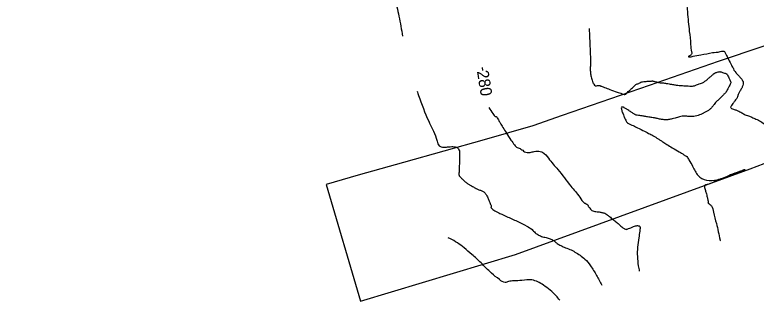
# Model space of a CAD drawing. Extents: x -478464 to -472469, y -1118040 to -1113785.
# Drawn here: x -476356.8 to -476101.8, y -1115350.3 to -1115251.7 of the extents above; entities that cross this region are included whole.
import ezdxf

# ---------------------------------------------------------------- set-up
doc = ezdxf.new("R2010")
doc.units = 0
for name, color, linetype in [('ObPÚ', 7, 'Continuous'), ('Vrstevnice_hlavni', 7, 'Continuous'), ('Vrstevnice_popis', 7, 'Continuous'), ('Vrstevnice_vedlejsi', 7, 'Continuous')]:
    doc.layers.add(name, color=color, linetype=linetype)

msp = doc.modelspace()

# ---------------------------------------------------------------- linework, layer by layer
at = {"layer": 'ObPÚ'}
msp.add_lwpolyline([(-476068.7, -1115252.31), (-476114.88, -1115267.73), (-476138.618, -1115276.003), (-476141.91, -1115277.15), (-476168.45, -1115286.39), (-476178.6, -1115289.93), (-476195.38, -1115294.7), (-476223.04, -1115302.55), (-476238.65, -1115306.98), (-476249.64, -1115310.1), (-476237.84, -1115350.34), (-476184.5, -1115334.29), (-476103.79, -1115304.74), (-476065.34, -1115290.09)], dxfattribs=at)
at = {"layer": 'Vrstevnice_hlavni'}
msp.add_line((-476196.015, -1115269.846), (-476195.861, -1115270.85), dxfattribs=at)
msp.add_spline([(-476193.757, -1115283.639), (-476192.399, -1115285.697), (-476191.876, -1115286.389), (-476191.509, -1115286.744), (-476191.298, -1115286.761), (-476191.153, -1115286.774), (-476191.075, -1115286.783), (-476191.063, -1115286.789), (-476190.853, -1115287.151), (-476190.446, -1115287.871), (-476189.842, -1115288.948), (-476188.923, -1115290.467), (-476187.688, -1115292.429), (-476186.137, -1115294.833), (-476184.891, -1115296.504), (-476183.948, -1115297.443), (-476183.309, -1115297.648), (-476182.68, -1115297.954), (-476182.06, -1115298.362), (-476181.45, -1115298.872), (-476180.595, -1115299.114), (-476179.497, -1115299.088), (-476178.155, -1115298.795), (-476176.997, -1115298.69), (-476176.025, -1115298.773), (-476175.238, -1115299.045), (-476173.224, -1115301.122), (-476169.984, -1115305.003), (-476165.518, -1115310.689), (-476162.449, -1115314.535), (-476160.779, -1115316.54), (-476160.507, -1115316.704), (-476160.264, -1115316.845), (-476160.048, -1115316.962), (-476159.86, -1115317.056), (-476159.707, -1115317.19), (-476159.59, -1115317.365), (-476159.508, -1115317.58), (-476159.311, -1115317.896), (-476158.998, -1115318.315), (-476158.57, -1115318.834), (-476158.007, -1115319.207), (-476157.308, -1115319.433), (-476156.473, -1115319.513), (-476155.76, -1115319.601), (-476155.169, -1115319.698), (-476154.699, -1115319.804), (-476154.303, -1115319.906), (-476153.978, -1115320.004), (-476153.727, -1115320.098), (-476153.145, -1115320.495), (-476152.232, -1115321.193), (-476150.988, -1115322.193), (-476149.831, -1115323.145), (-476148.761, -1115324.046), (-476147.778, -1115324.899), (-476147.017, -1115325.426), (-476146.478, -1115325.629), (-476146.16, -1115325.507), (-476145.635, -1115325.303), (-476144.904, -1115325.017), (-476143.967, -1115324.649), (-476143.233, -1115324.414), (-476142.702, -1115324.312), (-476142.375, -1115324.342), (-476142.123, -1115324.398), (-476141.945, -1115324.481), (-476141.842, -1115324.59), (-476141.767, -1115324.715), (-476141.722, -1115324.858), (-476141.705, -1115325.018), (-476141.842, -1115326.221), (-476142.131, -1115328.466), (-476142.574, -1115331.753), (-476142.636, -1115334.999), (-476142.32, -1115338.203), (-476141.962, -1115339.984)], degree=3, dxfattribs=at)
at = {"layer": 'Vrstevnice_vedlejsi'}
for points in [[(-476075.436, -1115157.873), (-476077.562, -1115158.907), (-476079.639, -1115159.964), (-476081.666, -1115161.045), (-476083.644, -1115162.149), (-476085.921, -1115163.289), (-476088.498, -1115164.465), (-476091.373, -1115165.676), (-476093.656, -1115166.843), (-476095.346, -1115167.967), (-476096.444, -1115169.047), (-476097.921, -1115170.165), (-476099.777, -1115171.319), (-476102.012, -1115172.511), (-476105.743, -1115173.677), (-476110.97, -1115174.816), (-476117.692, -1115175.928), (-476122.561, -1115177.005), (-476125.576, -1115178.045), (-476126.738, -1115179.05), (-476129.738, -1115180.989), (-476134.578, -1115183.864), (-476141.257, -1115187.673), (-476147.035, -1115190.356), (-476151.912, -1115191.911), (-476155.888, -1115192.338), (-476158.789, -1115192.754), (-476160.614, -1115193.159), (-476161.364, -1115193.552), (-476162.517, -1115193.939), (-476164.073, -1115194.319), (-476166.032, -1115194.693), (-476167.609, -1115195.158), (-476168.804, -1115195.715), (-476169.616, -1115196.364), (-476170.816, -1115197.116), (-476172.405, -1115197.973), (-476174.383, -1115198.934), (-476179.537, -1115202.555), (-476187.868, -1115208.836), (-476199.377, -1115217.776), (-476207.75, -1115223.932), (-476212.989, -1115227.302), (-476215.093, -1115227.888), (-476217.31, -1115229.046), (-476219.639, -1115230.776), (-476222.081, -1115233.079), (-476224.102, -1115235.091), (-476225.704, -1115236.812), (-476226.884, -1115238.243), (-476227.475, -1115239.561), (-476227.475, -1115240.767), (-476226.885, -1115241.861), (-476225.939, -1115245.662), (-476224.639, -1115252.17), (-476223.41, -1115259.087)], [(-476327.473, -1115168.696), (-476329.504, -1115168.15), (-476331.355, -1115167.757), (-476333.026, -1115167.517), (-476334.516, -1115167.429), (-476335.694, -1115167.418), (-476336.557, -1115167.482), (-476337.107, -1115167.623), (-476338.859, -1115167.867), (-476341.812, -1115168.215), (-476345.968, -1115168.668), (-476348.868, -1115168.973), (-476350.514, -1115169.133), (-476350.905, -1115169.146), (-476351.565, -1115169.254), (-476352.495, -1115169.457), (-476353.694, -1115169.755), (-476355.366, -1115170.663), (-476357.511, -1115172.179), (-476360.129, -1115174.306), (-476363.1, -1115176.798), (-476366.424, -1115179.657), (-476370.101, -1115182.883), (-476375.4, -1115186.443), (-476382.321, -1115190.337), (-476390.863, -1115194.566), (-476396.652, -1115197.445), (-476399.688, -1115198.974), (-476399.971, -1115199.154), (-476400.201, -1115199.316), (-476400.377, -1115199.461), (-476400.5, -1115199.588), (-476400.639, -1115199.703), (-476400.797, -1115199.808), (-476400.971, -1115199.902), (-476403.048, -1115202.383), (-476407.029, -1115207.252), (-476412.913, -1115214.508), (-476418.066, -1115221.099), (-476422.487, -1115227.024), (-476426.176, -1115232.285), (-476429.359, -1115236.354), (-476432.037, -1115239.231), (-476434.209, -1115240.916), (-476436.447, -1115242.554), (-476438.753, -1115244.145), (-476441.124, -1115245.69), (-476442.942, -1115247.528), (-476444.207, -1115249.66), (-476444.917, -1115252.086), (-476445.62, -1115255.263), (-476446.315, -1115259.192), (-476447.003, -1115263.872), (-476447.667, -1115266.918), (-476448.308, -1115268.33), (-476448.925, -1115268.107), (-476449.337, -1115267.958), (-476449.542, -1115267.883), (-476449.542, -1115267.884), (-476449.447, -1115268.421), (-476449.255, -1115269.495), (-476448.968, -1115271.106), (-476448.944, -1115271.994)], [(-476290.943, -1115168.232), (-476292.036, -1115168.129), (-476293.289, -1115168.17), (-476294.704, -1115168.355), (-476296.28, -1115168.684), (-476298.044, -1115169.506), (-476299.998, -1115170.82), (-476302.142, -1115172.626), (-476303.749, -1115173.838), (-476304.822, -1115174.454), (-476305.36, -1115174.476), (-476306.141, -1115174.653), (-476307.165, -1115174.987), (-476308.432, -1115175.476), (-476310.431, -1115176.469), (-476313.163, -1115177.965), (-476316.627, -1115179.965), (-476319.342, -1115180.948), (-476321.309, -1115180.916), (-476322.528, -1115179.868), (-476324.355, -1115178.896), (-476326.789, -1115178.002), (-476329.831, -1115177.184), (-476332.146, -1115176.734), (-476333.735, -1115176.651), (-476334.597, -1115176.934), (-476335.575, -1115177.335), (-476336.67, -1115177.853), (-476337.881, -1115178.489), (-476340.138, -1115179.828), (-476343.441, -1115181.87), (-476347.791, -1115184.616), (-476351.193, -1115186.546), (-476353.648, -1115187.661), (-476355.156, -1115187.959), (-476356.569, -1115188.49), (-476357.888, -1115189.253), (-476359.112, -1115190.247), (-476360.257, -1115191.198), (-476361.323, -1115192.106), (-476362.309, -1115192.972), (-476363.814, -1115193.968), (-476365.837, -1115195.095), (-476368.378, -1115196.353), (-476371.783, -1115197.918), (-476376.05, -1115199.79), (-476381.181, -1115201.968), (-476385.269, -1115204.296), (-476388.314, -1115206.773), (-476390.316, -1115209.399), (-476391.767, -1115211.232), (-476392.667, -1115212.272), (-476393.014, -1115212.519), (-476394.789, -1115214.333), (-476397.991, -1115217.713), (-476402.619, -1115222.659), (-476406.002, -1115226.323), (-476408.139, -1115228.705), (-476409.031, -1115229.805), (-476409.796, -1115230.781), (-476410.434, -1115231.632), (-476410.944, -1115232.36), (-476411.453, -1115232.976), (-476411.961, -1115233.481), (-476412.467, -1115233.874), (-476413.193, -1115235.547), (-476414.139, -1115238.502), (-476415.303, -1115242.737), (-476416.343, -1115247.381), (-476417.259, -1115252.434), (-476418.049, -1115257.897), (-476418.052, -1115258.256)], [(-476125.929, -1115243.884), (-476125.807, -1115246.158), (-476125.427, -1115250.782), (-476124.774, -1115257.383), (-476124.301, -1115261.931), (-476124.008, -1115264.426), (-476123.894, -1115264.868), (-476123.981, -1115265.246), (-476124.269, -1115265.56), (-476124.757, -1115265.811), (-476125.029, -1115265.996), (-476125.083, -1115266.115), (-476124.92, -1115266.169), (-476123.491, -1115265.956), (-476120.797, -1115265.476), (-476116.836, -1115264.728), (-476114.123, -1115264.363), (-476112.657, -1115264.382), (-476112.438, -1115264.783), (-476111.966, -1115265.692), (-476111.241, -1115267.111), (-476110.263, -1115269.038), (-476109.58, -1115270.343), (-476109.193, -1115271.027), (-476109.102, -1115271.089), (-476109.038, -1115271.136), (-476109.003, -1115271.169), (-476108.995, -1115271.186), (-476108.962, -1115271.248), (-476108.904, -1115271.357), (-476108.821, -1115271.512), (-476108.502, -1115271.894), (-476107.946, -1115272.505), (-476107.155, -1115273.343), (-476106.601, -1115274.081), (-476106.285, -1115274.719), (-476106.206, -1115275.258), (-476106.359, -1115275.986), (-476106.744, -1115276.905)], [(-476159.242, -1115256.374), (-476159.054, -1115259.908), (-476158.82, -1115265.295), (-476158.75, -1115268.706), (-476158.845, -1115270.139), (-476158.769, -1115271.604), (-476158.523, -1115273.101), (-476158.106, -1115274.629), (-476157.613, -1115275.635), (-476157.044, -1115276.119), (-476156.398, -1115276.081), (-476155.961, -1115276.055), (-476155.733, -1115276.04), (-476155.713, -1115276.036), (-476155.581, -1115276.081), (-476155.338, -1115276.173), (-476154.983, -1115276.314), (-476153.911, -1115276.714), (-476152.122, -1115277.373), (-476149.617, -1115278.29), (-476147.877, -1115278.87), (-476146.903, -1115279.111), (-476146.694, -1115279.015), (-476146.533, -1115278.92), (-476146.42, -1115278.827), (-476146.354, -1115278.736), (-476146.034, -1115278.42), (-476145.458, -1115277.878), (-476144.627, -1115277.111), (-476144.009, -1115276.53), (-476143.606, -1115276.135), (-476143.416, -1115275.928), (-476143.115, -1115275.721), (-476142.7, -1115275.515), (-476142.174, -1115275.31), (-476141.777, -1115275.132), (-476141.512, -1115274.98), (-476141.376, -1115274.855), (-476140.853, -1115274.744), (-476139.943, -1115274.647), (-476138.645, -1115274.565), (-476137.773, -1115274.512), (-476137.326, -1115274.488), (-476137.304, -1115274.493), (-476137.022, -1115274.564), (-476136.479, -1115274.699), (-476135.676, -1115274.9), (-476135.01, -1115275.037), (-476134.48, -1115275.109), (-476134.087, -1115275.117), (-476133.301, -1115275.213), (-476132.123, -1115275.399), (-476130.553, -1115275.673), (-476129.267, -1115275.873), (-476128.264, -1115275.998), (-476127.545, -1115276.049), (-476126.691, -1115276.105), (-476125.702, -1115276.169), (-476124.578, -1115276.238), (-476123.673, -1115276.222), (-476122.988, -1115276.122), (-476122.522, -1115275.938), (-476121.968, -1115275.735), (-476121.325, -1115275.516), (-476120.594, -1115275.279), (-476119.818, -1115274.872), (-476118.996, -1115274.295), (-476118.13, -1115273.548), (-476117.407, -1115272.922), (-476116.827, -1115272.417), (-476116.391, -1115272.033), (-476115.924, -1115271.733), (-476115.425, -1115271.516), (-476114.896, -1115271.383), (-476114.504, -1115271.301), (-476114.247, -1115271.269), (-476114.127, -1115271.287), (-476113.822, -1115271.374), (-476113.331, -1115271.529), (-476112.656, -1115271.752), (-476112.177, -1115271.921), (-476111.894, -1115272.035), (-476111.807, -1115272.094), (-476111.623, -1115272.416), (-476111.341, -1115273)], [(-476111.341, -1115273), (-476110.962, -1115273.848), (-476110.694, -1115274.441), (-476110.537, -1115274.78), (-476110.491, -1115274.865), (-476110.47, -1115274.959), (-476110.475, -1115275.062), (-476110.506, -1115275.174), (-476110.69, -1115275.573), (-476111.03, -1115276.26), (-476111.524, -1115277.233), (-476111.877, -1115277.912), (-476112.088, -1115278.296), (-476112.158, -1115278.386), (-476112.514, -1115278.752), (-476113.156, -1115279.397), (-476114.085, -1115280.319), (-476114.761, -1115280.979), (-476115.186, -1115281.379), (-476115.36, -1115281.517), (-476115.713, -1115281.919), (-476116.247, -1115282.585), (-476116.962, -1115283.514), (-476117.741, -1115284.291), (-476118.584, -1115284.915), (-476119.493, -1115285.387), (-476120.392, -1115285.812), (-476121.284, -1115286.191), (-476122.167, -1115286.523), (-476123.251, -1115286.707), (-476124.536, -1115286.741), (-476126.022, -1115286.628), (-476127.231, -1115286.643), (-476128.162, -1115286.786), (-476128.816, -1115287.059), (-476129.654, -1115287.316), (-476130.678, -1115287.555), (-476131.887, -1115287.779), (-476133.124, -1115287.833), (-476134.388, -1115287.719), (-476135.68, -1115287.435), (-476136.751, -1115287.215), (-476137.602, -1115287.058), (-476138.232, -1115286.963), (-476139.134, -1115286.827), (-476140.308, -1115286.649), (-476141.754, -1115286.429), (-476142.752, -1115286.26), (-476143.303, -1115286.142), (-476143.406, -1115286.075), (-476143.876, -1115285.775), (-476144.711, -1115285.24), (-476145.912, -1115284.47), (-476146.719, -1115283.95), (-476147.131, -1115283.678), (-476147.149, -1115283.654), (-476147.194, -1115283.626), (-476147.267, -1115283.594), (-476147.366, -1115283.557), (-476147.542, -1115283.533), (-476147.795, -1115283.522), (-476148.124, -1115283.524), (-476148.141, -1115284.035), (-476147.848, -1115285.056), (-476147.243, -1115286.586), (-476146.785, -1115287.691), (-476146.474, -1115288.372), (-476146.31, -1115288.628), (-476146.156, -1115288.817), (-476146.012, -1115288.938), (-476145.878, -1115288.992), (-476144.948, -1115289.442), (-476143.224, -1115290.289), (-476140.705, -1115291.532), (-476138.75, -1115292.524), (-476137.361, -1115293.265), (-476136.537, -1115293.756), (-476135.685, -1115294.285), (-476134.806, -1115294.853), (-476133.899, -1115295.46), (-476132.503, -1115296.342), (-476130.618, -1115297.498), (-476128.243, -1115298.929), (-476126.641, -1115299.885), (-476125.811, -1115300.366), (-476125.755, -1115300.372), (-476125.7, -1115300.405), (-476125.646, -1115300.464), (-476125.594, -1115300.551), (-476124.922, -1115301.679), (-476123.631, -1115303.848), (-476121.721, -1115307.059), (-476118.902, -1115308.612), (-476115.176, -1115308.508), (-476110.541, -1115306.747), (-476107.432, -1115305.567), (-476105.848, -1115304.97)], [(-476106.744, -1115276.905), (-476107.361, -1115278.014), (-476107.805, -1115278.877), (-476108.078, -1115279.493), (-476108.177, -1115279.862), (-476108.25, -1115280.122), (-476108.297, -1115280.271), (-476108.317, -1115280.311), (-476108.573, -1115280.647), (-476109.065, -1115281.28), (-476109.793, -1115282.209), (-476110.279, -1115282.913), (-476110.525, -1115283.392), (-476110.528, -1115283.645), (-476110.197, -1115283.923), (-476109.532, -1115284.226), (-476108.532, -1115284.553), (-476107.69, -1115284.894), (-476107.005, -1115285.251), (-476106.478, -1115285.622), (-476105.861, -1115285.956), (-476105.153, -1115286.251), (-476104.354, -1115286.507), (-476103.257, -1115286.96), (-476101.863, -1115287.61), (-476100.172, -1115288.455), (-476098.717, -1115289.598), (-476097.498, -1115291.039), (-476096.516, -1115292.777), (-476095.725, -1115294.323), (-476095.126, -1115295.678), (-476094.718, -1115296.841), (-476094.281, -1115297.767), (-476093.815, -1115298.456), (-476093.319, -1115298.907), (-476093.04, -1115299.473), (-476092.976, -1115300.153), (-476093.128, -1115300.947), (-476092.975, -1115301.971), (-476092.517, -1115303.223), (-476091.755, -1115304.704), (-476090.913, -1115306.661), (-476089.99, -1115309.094), (-476088.988, -1115312.004), (-476088.293, -1115314.278), (-476087.906, -1115315.919), (-476087.826, -1115316.925), (-476087.506, -1115318.414), (-476087.193, -1115319.54)], [(-476218.376, -1115278.038), (-476217.875, -1115279.456), (-476214.425, -1115288.313), (-476211.835, -1115294.229), (-476210.106, -1115297.205), (-476209.237, -1115297.241), (-476208.349, -1115297.236), (-476207.441, -1115297.189), (-476206.512, -1115297.099), (-476205.696, -1115297.136), (-476204.991, -1115297.297), (-476204.399, -1115297.584), (-476203.999, -1115298.149), (-476203.792, -1115298.991), (-476203.779, -1115300.111), (-476203.805, -1115301.478), (-476203.871, -1115303.093), (-476203.978, -1115304.956), (-476204.004, -1115306.275), (-476203.949, -1115307.051), (-476203.815, -1115307.284), (-476203.415, -1115307.714), (-476202.75, -1115308.342), (-476201.819, -1115309.168), (-476200.943, -1115309.859), (-476200.122, -1115310.415), (-476199.355, -1115310.837), (-476198.758, -1115311.169), (-476198.331, -1115311.411), (-476198.073, -1115311.564), (-476197.577, -1115311.782), (-476196.841, -1115312.065), (-476195.867, -1115312.414), (-476195.041, -1115313.077), (-476194.362, -1115314.054), (-476193.831, -1115315.346), (-476193.423, -1115316.323), (-476193.136, -1115316.986), (-476192.972, -1115317.333), (-476192.894, -1115317.625), (-476192.903, -1115317.861)], [(-476105.848, -1115304.97), (-476105.79, -1115304.953), (-476105.742, -1115304.95), (-476105.706, -1115304.96), (-476105.681, -1115304.983), (-476105.665, -1115305.007), (-476105.66, -1115305.032), (-476105.665, -1115305.057), (-476105.684, -1115305.087), (-476105.717, -1115305.122), (-476105.765, -1115305.16), (-476107.334, -1115305.771), (-476110.427, -1115306.953), (-476115.042, -1115308.707), (-476118.091, -1115309.993), (-476119.575, -1115310.812), (-476119.492, -1115311.162), (-476119.302, -1115311.898), (-476119.003, -1115313.019), (-476118.597, -1115314.525), (-476118.349, -1115315.58), (-476118.261, -1115316.183), (-476118.333, -1115316.335), (-476118.325, -1115316.469), (-476118.238, -1115316.585), (-476118.073, -1115316.683), (-476117.836, -1115316.872), (-476117.529, -1115317.152), (-476117.151, -1115317.523), (-476116.463, -1115319.666), (-476115.466, -1115323.582), (-476114.16, -1115329.271), (-476114.085, -1115329.578)], [(-476192.903, -1115317.861), (-476192.999, -1115318.042), (-476192.816, -1115318.327), (-476192.354, -1115318.716), (-476191.613, -1115319.21), (-476189.891, -1115320.089), (-476187.188, -1115321.354), (-476183.505, -1115323.005), (-476180.713, -1115324.453), (-476178.814, -1115325.697), (-476177.806, -1115326.737), (-476176.612, -1115327.549), (-476175.23, -1115328.132), (-476173.662, -1115328.486), (-476172.346, -1115328.961), (-476171.282, -1115329.555), (-476170.47, -1115330.27), (-476169.305, -1115330.996), (-476167.786, -1115331.732), (-476165.913, -1115332.48), (-476164.102, -1115333.412), (-476162.353, -1115334.527), (-476160.666, -1115335.826), (-476158.775, -1115338.132), (-476156.681, -1115341.444), (-476154.893, -1115344.811)], [(-476169.317, -1115349.984), (-476170.582, -1115348.511), (-476174.959, -1115344.81), (-476178.893, -1115343.028), (-476182.384, -1115343.164), (-476185.085, -1115343.353), (-476186.997, -1115343.594), (-476188.119, -1115343.887), (-476190.063, -1115342.911), (-476192.828, -1115340.664), (-476196.414, -1115337.147), (-476199.562, -1115334.239), (-476202.271, -1115331.942), (-476204.542, -1115330.254), (-476207.149, -1115328.799), (-476207.747, -1115328.526)]]:
    msp.add_spline(points, degree=3, dxfattribs=at)

# ---------------------------------------------------------------- texts
at = {"layer": 'Vrstevnice_popis'}
msp.add_text(' 280 ', height=4, rotation=279.08544, dxfattribs=at).set_placement((-476198.078, -1115269.663))

doc.saveas('drawing.dxf')
